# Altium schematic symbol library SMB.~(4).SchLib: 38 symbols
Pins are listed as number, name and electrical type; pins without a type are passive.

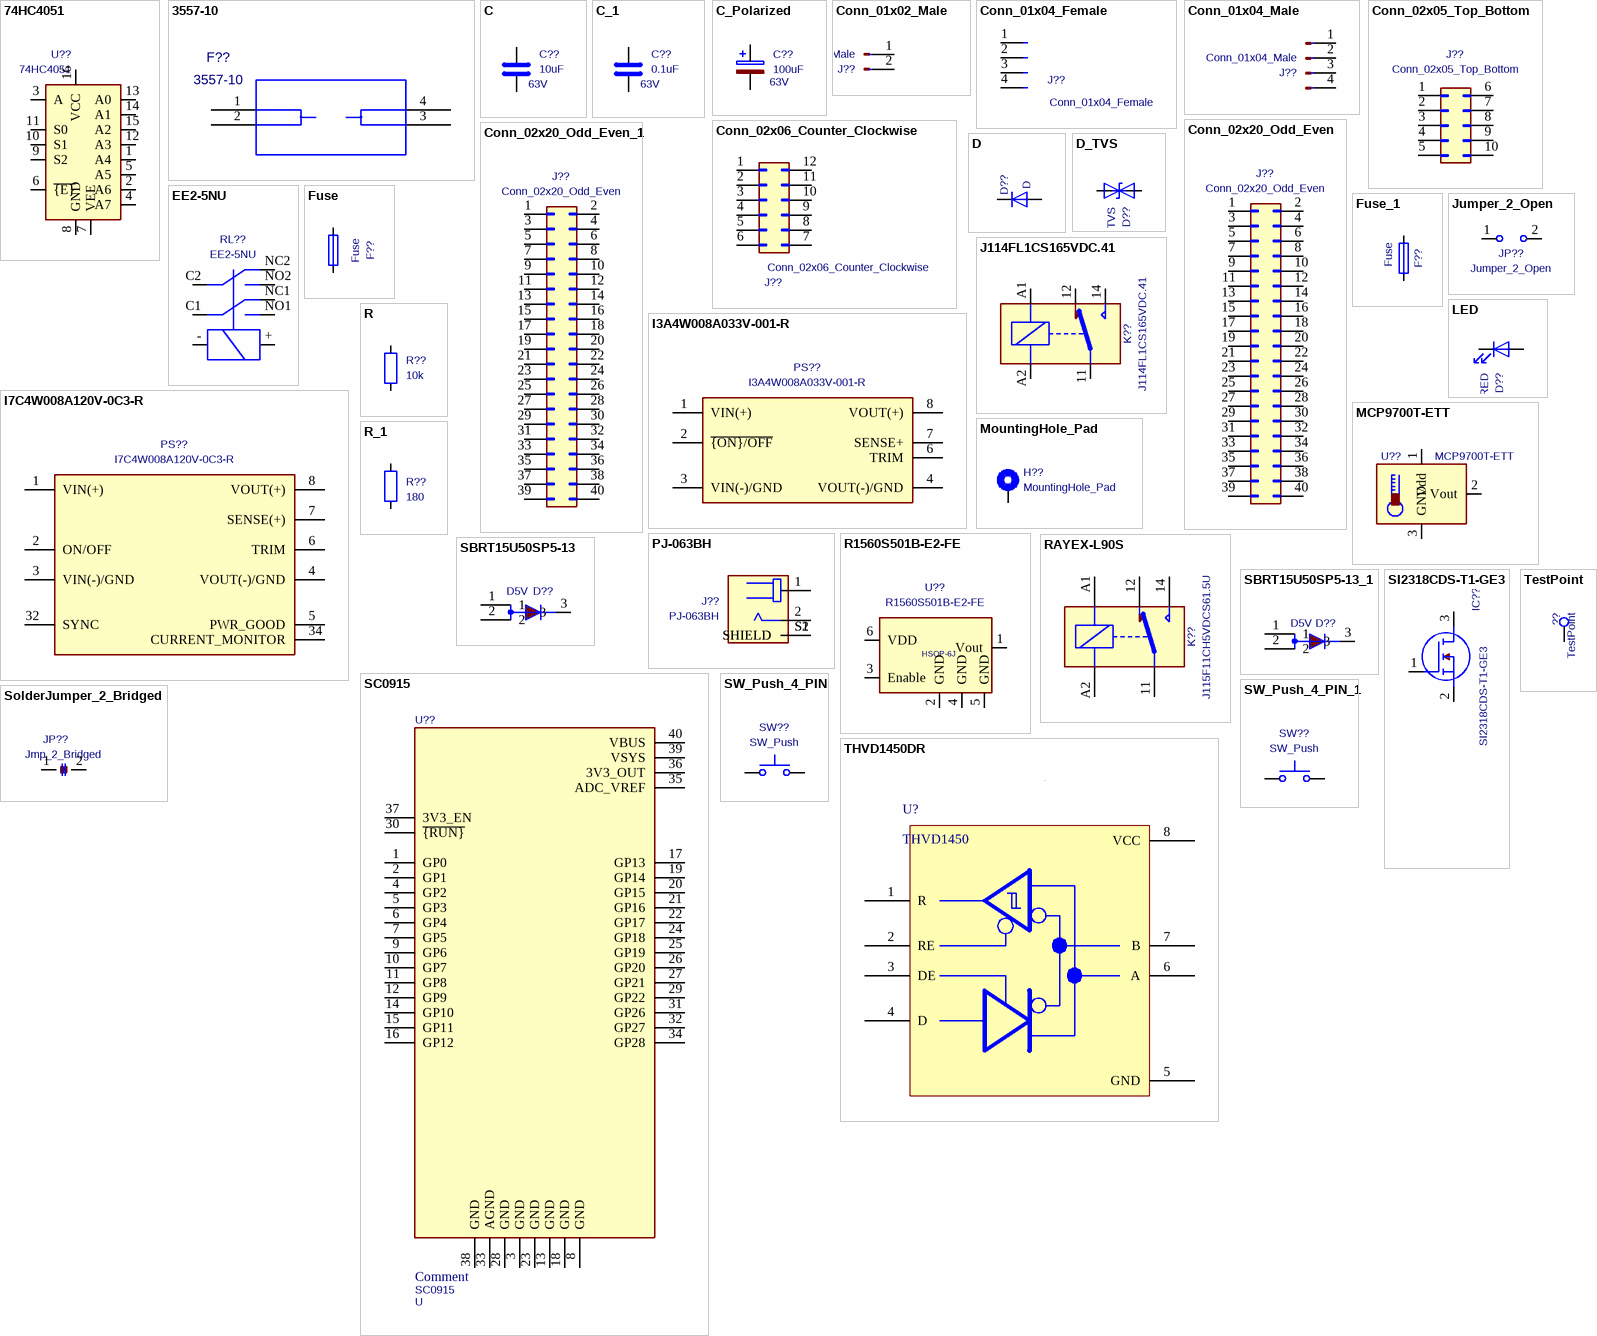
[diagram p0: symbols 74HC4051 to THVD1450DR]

## 74HC4051
designator U??, comment value 74HC4051  (hidden comment: Comment)
footprint TSSOP-16_4.4x5mm_P0.65mm
pins: 1 A4, 2 A6, 3 A, 4 A7, 5 A5, 6 ~{{E}}, 7 VEE, 8 GND, 9 S2, 10 S1, 11 S0, 12 A3, 13 A0, 14 A1, 15 A2, 16 VCC

## 3557-10
designator F??, comment value 3557-10  (hidden comment: Comment)
footprint 3557-10
pins: 1, 2, 3, 4

## C
designator C??, comment value 10uF  Voltage: 63V  (hidden comment: Comment)
footprint C_1210_3225Metric
pins: 1, 2

## C_1
designator C??, comment value 0.1uF  Voltage: 63V  (hidden comment: Comment)
footprint C_1206_3216Metric
pins: 1, 2

## C_Polarized
designator C??, comment value 100uF  Voltage: 63V  (hidden comment: Comment)
footprint CP_Elec_10x12.6
pins: 1, 2

## Conn_01x02_Male
designator J??, comment value Conn_01x02_Male  (hidden comment: Comment)
footprint 1843606
pins: 1 Pin_1, 2 Pin_2

## Conn_01x04_Female
designator J??, comment value Conn_01x04_Female  (hidden comment: Comment)
footprint PinHeader_1x04_P2.54mm_Vertical
pins: 1 Pin_1, 2 Pin_2, 3 Pin_3, 4 Pin_4

## Conn_01x04_Male
designator J??, comment value Conn_01x04_Male  (hidden comment: Comment)
footprint 1924321
pins: 1 Pin_1, 2 Pin_2, 3 Pin_3, 4 Pin_4

## Conn_02x05_Top_Bottom
designator J??, comment value Conn_02x05_Top_Bottom  (hidden comment: Comment)
footprint PinSocket_2x05_P2.54mm_Vertical
pins: 1 Pin_1, 2 Pin_2, 3 Pin_3, 4 Pin_4, 5 Pin_5, 6 Pin_6, 7 Pin_7, 8 Pin_8, 9 Pin_9, 10 Pin_10

## Conn_02x06_Counter_Clockwise
designator J??, comment value Conn_02x06_Counter_Clockwise  (hidden comment: Comment)
footprint PinHeader_2x06_P2.54mm_Vertical
pins: 1 Pin_1, 2 Pin_2, 3 Pin_3, 4 Pin_4, 5 Pin_5, 6 Pin_6, 7 Pin_7, 8 Pin_8, 9 Pin_9, 10 Pin_10, 11 Pin_11, 12 Pin_12

## Conn_02x20_Odd_Even
designator J??, comment value Conn_02x20_Odd_Even  (hidden comment: Comment)
footprint PinHeader_2x20_P2.54mm_Horizontal
pins: 1 Pin_1, 2 Pin_2, 3 Pin_3, 4 Pin_4, 5 Pin_5, 6 Pin_6, 7 Pin_7, 8 Pin_8, 9 Pin_9, 10 Pin_10, 11 Pin_11, 12 Pin_12, 13 Pin_13, 14 Pin_14, 15 Pin_15, 16 Pin_16, 17 Pin_17, 18 Pin_18, 19 Pin_19, 20 Pin_20, 21 Pin_21, 22 Pin_22, 23 Pin_23, 24 Pin_24, 25 Pin_25, 26 Pin_26, 27 Pin_27, 28 Pin_28, 29 Pin_29, 30 Pin_30, 31 Pin_31, 32 Pin_32, 33 Pin_33, 34 Pin_34, 35 Pin_35, 36 Pin_36, 37 Pin_37, 38 Pin_38, 39 Pin_39, 40 Pin_40

## Conn_02x20_Odd_Even_1
designator J??, comment value Conn_02x20_Odd_Even  (hidden comment: Comment)
footprint PinHeader_2x20_P2.54mm_Vertical
pins: 1 Pin_1, 2 Pin_2, 3 Pin_3, 4 Pin_4, 5 Pin_5, 6 Pin_6, 7 Pin_7, 8 Pin_8, 9 Pin_9, 10 Pin_10, 11 Pin_11, 12 Pin_12, 13 Pin_13, 14 Pin_14, 15 Pin_15, 16 Pin_16, 17 Pin_17, 18 Pin_18, 19 Pin_19, 20 Pin_20, 21 Pin_21, 22 Pin_22, 23 Pin_23, 24 Pin_24, 25 Pin_25, 26 Pin_26, 27 Pin_27, 28 Pin_28, 29 Pin_29, 30 Pin_30, 31 Pin_31, 32 Pin_32, 33 Pin_33, 34 Pin_34, 35 Pin_35, 36 Pin_36, 37 Pin_37, 38 Pin_38, 39 Pin_39, 40 Pin_40

## D
designator D??, comment value D  (hidden comment: Comment)
footprint D_SOD-123F
pins: 1 K, 2 A

## D_TVS
designator D??, comment value D_TVS  (hidden comment: Comment)
footprint D_SMA
pins: 1 A1, 2 A2

## EE2-5NU
designator RL??, comment value EE2-5NU  (hidden comment: Comment)
footprint EE2-5NU
pins: +, -, C1, C2, NC1, NC2, NO1, NO2

## Fuse
designator F??, comment value Fuse  (hidden comment: Comment)
footprint FUSC9830X318N
pins: 1, 2

## Fuse_1
designator F??, comment value Fuse  (hidden comment: Comment)
footprint Fuse_1206_3216Metric_Pad1.42x1.75mm_HandSolder
pins: 1, 2

## I3A4W008A033V-001-R
designator PS??, comment value I3A4W008A033V-001-R  (hidden comment: Comment)
MANUFACTURER: TDK-Lambda
footprint CONV_I3A4W008A033V-001-R
pins: 1 VIN(+), 2 ~{{ON}/OFF}, 3 VIN(-)/GND, 4 VOUT(-)/GND, 6 TRIM, 7 SENSE+, 8 VOUT(+)

## I7C4W008A120V-0C3-R
designator PS??, comment value I7C4W008A120V-0C3-R  (hidden comment: Comment)
Power Supply Module; MANUFACTURER: TDK; SNAPEDA_PN: i7C4W012A050V-0C3-R
footprint CONV_I7C4W008A120V-0C3-R
pins: 1 VIN(+), 2 ON/OFF, 3 VIN(-)/GND, 4 VOUT(-)/GND, 5 PWR_GOOD, 6 TRIM, 7 SENSE(+), 8 VOUT(+), 32 SYNC, 34 CURRENT_MONITOR

## J114FL1CS165VDC.41
designator K??, comment value J114FL1CS165VDC.41  (hidden comment: Comment)
footprint Big Pads - Relay_SPDT_Schrack-RT1-16A-FormC_RM5mm
pins: 11, 12, 14, A1, A2

## Jumper_2_Open
designator JP??, comment value Jumper_2_Open  (hidden comment: Comment)
footprint PinHeader_1x02_P2.54mm_Vertical
pins: 1 A, 2 B

## LED
designator D??, comment value RED  (hidden comment: Comment)
footprint LED_1206_3216Metric
pins: 1 K, 2 A

## MCP9700T-ETT
designator U??, comment value MCP9700T-ETT  (hidden comment: Comment)
footprint SOT-23
pins: 1 Vdd, 2 Vout, 3 GND

## MountingHole_Pad
designator H??, comment value MountingHole_Pad  (hidden comment: Comment)
footprint MountingHole_3.2mm_M3_DIN965_Pad
pins: 1

## PJ-063BH
designator J??, comment value PJ-063BH  (hidden comment: Comment)
MANUFACTURER: CUI INC
footprint CUI_PJ-063BH
pins: 1, 2, S1 SHIELD, S2 SHIELD

## R
designator R??, comment value 10k  (hidden comment: Comment)
footprint R_1206_3216Metric
pins: 1, 2

## R1560S501B-E2-FE
designator U??, comment value R1560S501B-E2-FE  (hidden comment: Comment)
footprint HSOP-6J
pins: 1 Vout, 2 GND, 3 Enable, 4 GND, 5 GND, 6 VDD

## R_1
designator R??, comment value 180  (hidden comment: Comment)
footprint RES_3540_TEC
pins: 1, 2

## RAYEX-L90S
designator K??, comment value J115F11CH5VDCS61.5U  (hidden comment: Comment)
footprint Relay_SPDT_RAYEX-L90S
pins: 11, 12, 14, A1, A2

## SBRT15U50SP5-13
designator D??, comment value D5V  (hidden comment: Comment)
footprint POWERDI5_DIO
pins: 1, 2, 3

## SBRT15U50SP5-13_1
designator D??, comment value D5V  (hidden comment: Comment)
footprint POWERDI5_DIO
pins: 1, 2, 3

## SC0915
designator U??, comment Comment  value SC0915  Reference: U
MANUFACTURER: Raspberry Pi
footprint MODULE_SCO915_Custom_HeaderStyle
pins: 1 GP0, 2 GP1, 3 GND, 4 GP2, 5 GP3, 6 GP4, 7 GP5, 8 GND, 9 GP6, 10 GP7, 11 GP8, 12 GP9, 13 GND, 14 GP10, 15 GP11, 16 GP12, 17 GP13, 18 GND, 19 GP14, 20 GP15, 21 GP16, 22 GP17, 23 GND, 24 GP18, 25 GP19, 26 GP20, 27 GP21, 28 GND, 29 GP22, 30 ~{{RUN}}, 31 GP26, 32 GP27, 33 AGND, 34 GP28, 35 ADC_VREF, 36 3V3_OUT, 37 3V3_EN, 38 GND, 39 VSYS, 40 VBUS

## SI2318CDS-T1-GE3
designator IC??, comment value SI2318CDS-T1-GE3  (hidden comment: Comment)
MANUFACTURER_NAME: Vishay
footprint SOT95P237X112-3N
pins: 1, 2, 3

## SolderJumper_2_Bridged
designator JP??, comment value Jmp_2_Bridged  (hidden comment: Comment)
footprint SolderJumper-2_P1.3mm_Bridged_Pad1.0x1.5mm
pins: 1 A, 2 B

## SW_Push_4_PIN
designator SW??, comment value SW_Push  (hidden comment: Comment)
footprint SW_TL3305BF260QG
pins: 1, 2

## SW_Push_4_PIN_1
designator SW??, comment value SW_Push  (hidden comment: Comment)
footprint SW_TL3305BF260QG
pins: 1, 2

## TestPoint
designator ??, comment value TestPoint  (hidden comment: Comment)
footprint TestPoint_Pad_D1.0mm
pins: 1

## THVD1450DR
designator U?, comment THVD1450
Line Transceiver, 1 Func, 1 Driver, 1 Rcvr, PDSO8; Manufacturer: Texas Instruments; Manufacturer Part Number: THVD1450DR; Package Body Material: Plastic; Differential Output: Yes; Driver Number of Bits: 1; Input Characteristics: DIFFERENTIAL SCHMITT TRIGGER; Receive Delay-Max: 40ns; Max Supply Voltage: 5.5V; Min Supply Voltage: 3V; Nominal Supply Voltage: 5V; Transmit Delay-Max: 20ns
pins: 1 R, 2 RE, 3 DE, 4 D, 5 GND, 6 A, 7 B, 8 VCC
